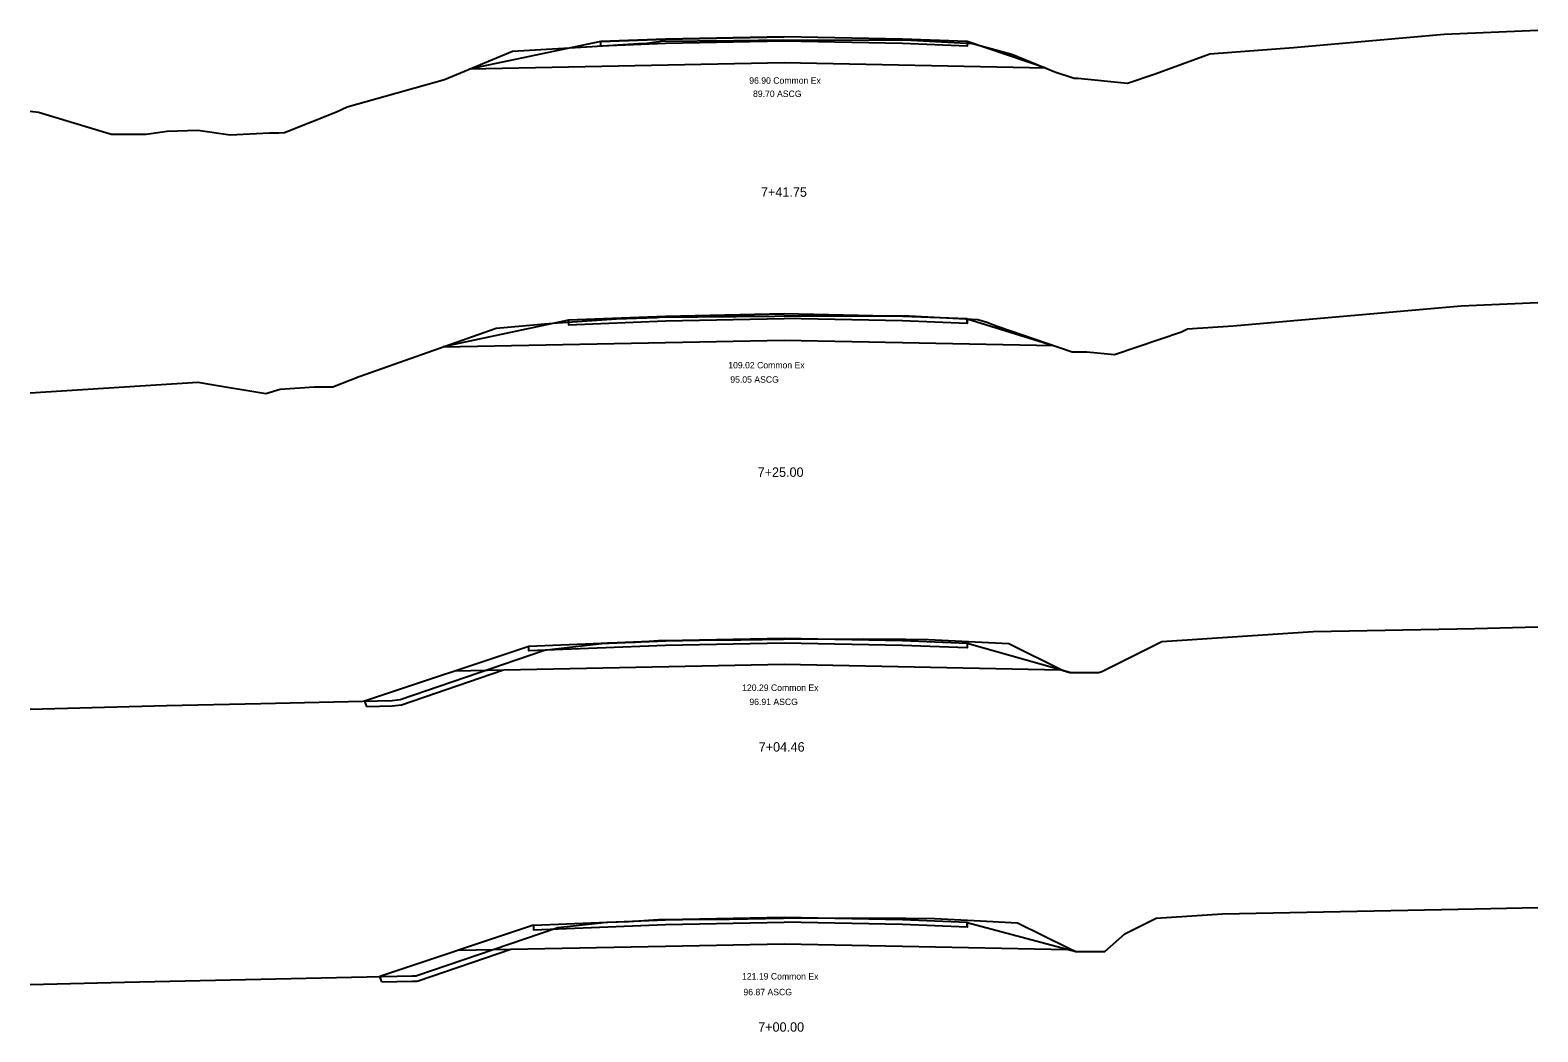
# Model space of a CAD drawing. Extents: x 2194004 to 2194525, y 863888 to 863998.
# Drawn here: x 2194385 to 2194525, y 863895.1 to 863988 of the extents above; entities that cross this region are included whole.
import ezdxf

# ---------------------------------------------------------------- set-up
doc = ezdxf.new("R2010")
doc.units = 0
for name, color, linetype in [('Approach', 7, 'Continuous'), ('H_V ANNOTATION', 7, 'Continuous'), ('S_Roadway_Centerline', 7, 'Continuous'), ('TEMPLATE', 7, 'Continuous')]:
    doc.layers.add(name, color=color, linetype=linetype)

msp = doc.modelspace()

# ---------------------------------------------------------------- linework, layer by layer
at = {"layer": 'S_Roadway_Centerline'}
for points in [[(2194384.99, 863980.53), (2194385.76, 863980.43), (2194392.02, 863978.54), (2194392.54, 863978.37), (2194395.76, 863978.39), (2194397.71, 863978.66), (2194400.57, 863978.76), (2194403.35, 863978.34), (2194403.57, 863978.33), (2194407.22, 863978.51), (2194408.07, 863978.51), (2194408.59, 863978.55), (2194413.42, 863980.46), (2194414.43, 863980.92), (2194423.45, 863983.47), (2194429.77, 863986.08), (2194437.17, 863986.52), (2194441.49, 863986.81), (2194442.24, 863986.84), (2194443.54, 863987.01), (2194450.34, 863987.07), (2194454.91, 863987.14), (2194459.64, 863987.12), (2194466.23, 863987.13), (2194468.49, 863987.01), (2194472.5, 863986.8), (2194476.14, 863985.8), (2194480.13, 863984.18), (2194481.92, 863983.57), (2194482.27, 863983.57), (2194486.89, 863983.12), (2194489.46, 863983.99), (2194494.52, 863985.83), (2194502.3, 863986.42), (2194516.28, 863987.66), (2194524.99, 863988.04)], [(2194384.99, 863954.36), (2194400.57, 863955.36), (2194401.83, 863955.13), (2194406.87, 863954.31), (2194408.21, 863954.7), (2194411.4, 863954.92), (2194413.08, 863954.93), (2194415.55, 863955.9), (2194428.25, 863960.36), (2194433.48, 863960.84), (2194439.44, 863961.24), (2194443.19, 863961.37), (2194443.42, 863961.4), (2194454.11, 863961.5), (2194454.96, 863961.51), (2194455.83, 863961.51), (2194466.22, 863961.53), (2194466.62, 863961.51), (2194472.97, 863961.18), (2194473.83, 863960.94), (2194474.78, 863960.56), (2194481.74, 863958.17), (2194483.1, 863958.17), (2194485.69, 863957.92), (2194491.9, 863960.03), (2194492.45, 863960.3), (2194496.68, 863960.58), (2194517.88, 863962.46), (2194524.99, 863962.76)], [(2194384.99, 863925.02), (2194397.64, 863925.35), (2194406.42, 863925.54), (2194418.59, 863925.82), (2194419.35, 863925.91), (2194432.66, 863930.45), (2194432.83, 863930.51), (2194432.96, 863930.52), (2194438.59, 863931.16), (2194441.16, 863931.24), (2194443.34, 863931.37), (2194450.98, 863931.44), (2194454.95, 863931.51), (2194462.37, 863931.53), (2194466.28, 863931.5), (2194468.39, 863931.48), (2194472.75, 863931.25), (2194475.86, 863931.1), (2194480.9, 863928.61), (2194481.52, 863928.4), (2194484.11, 863928.41), (2194484.22, 863928.4), (2194484.5, 863928.5), (2194490.06, 863931.29), (2194504.11, 863932.21), (2194519.14, 863932.5), (2194524.99, 863932.64)], [(2194384.99, 863899.44), (2194393.74, 863899.67), (2194420.46, 863900.26), (2194420.78, 863900.27), (2194420.83, 863900.27), (2194420.89, 863900.28), (2194420.89, 863900.28), (2194433.8, 863904.69), (2194434, 863904.73), (2194438.54, 863905.24), (2194440.57, 863905.31), (2194443.32, 863905.47), (2194449.92, 863905.53), (2194454.95, 863905.62), (2194461.36, 863905.63), (2194466.29, 863905.6), (2194468.97, 863905.57), (2194472.65, 863905.38), (2194476.66, 863905.18), (2194481.44, 863902.83), (2194482.09, 863902.5), (2194484.53, 863902.51), (2194484.77, 863902.5), (2194486.65, 863904.16), (2194489.54, 863905.62), (2194495.71, 863906.02), (2194519.17, 863906.47), (2194524.99, 863906.6)]]:
    msp.add_lwpolyline(points, dxfattribs=at)
at = {"layer": 'TEMPLATE'}
for p, q in [((2194437.99, 863986.97), (2194425.76, 863984.42)), ((2194437.99, 863986.97), (2194443.99, 863987.21)), ((2194443.99, 863987.21), (2194437.99, 863986.97)), ((2194437.99, 863986.97), (2194437.99, 863986.97)), ((2194443.99, 863987.21), (2194454.99, 863987.43)), ((2194454.99, 863987.43), (2194443.99, 863987.21)), ((2194454.99, 863987.01), (2194443.99, 863986.79)), ((2194465.99, 863987.21), (2194454.99, 863987.43)), ((2194465.99, 863986.79), (2194454.99, 863987.01)), ((2194471.99, 863986.97), (2194465.99, 863987.21)), ((2194479.29, 863984.52), (2194471.99, 863986.97)), ((2194454.99, 863985.01), (2194425.76, 863984.42)), ((2194479.29, 863984.52), (2194454.99, 863985.01)), ((2194434.97, 863961.11), (2194423.34, 863958.64)), ((2194443.99, 863961.47), (2194434.97, 863961.11)), ((2194443.99, 863961.47), (2194454.99, 863961.69)), ((2194454.99, 863961.69), (2194443.99, 863961.47)), ((2194443.99, 863961.05), (2194454.99, 863961.27)), ((2194465.99, 863961.47), (2194454.99, 863961.69)), ((2194465.99, 863961.05), (2194454.99, 863961.27)), ((2194471.99, 863961.23), (2194465.99, 863961.47)), ((2194471.99, 863961.23), (2194479.99, 863958.77)), ((2194431.28, 863930.84), (2194416.04, 863925.76)), ((2194443.99, 863931.35), (2194431.28, 863930.84)), ((2194437.99, 863931.11), (2194443.99, 863931.35)), ((2194437.99, 863931.11), (2194437.99, 863931.11)), ((2194443.99, 863931.35), (2194454.99, 863931.57)), ((2194454.99, 863931.57), (2194443.99, 863931.35)), ((2194454.99, 863931.15), (2194443.99, 863930.93)), ((2194465.99, 863931.35), (2194454.99, 863931.57)), ((2194465.99, 863930.93), (2194454.99, 863931.15)), ((2194471.99, 863931.11), (2194465.99, 863931.35)), ((2194481.52, 863928.4), (2194471.99, 863931.11)), ((2194454.99, 863929.15), (2194424.38, 863928.54)), ((2194480.7, 863928.63), (2194454.99, 863929.15)), ((2194416.04, 863925.76), (2194416.21, 863925.26)), ((2194443.99, 863905.44), (2194454.99, 863905.66)), ((2194454.99, 863905.66), (2194443.99, 863905.44)), ((2194443.99, 863905.02), (2194454.99, 863905.24)), ((2194465.99, 863905.44), (2194454.99, 863905.66)), ((2194465.99, 863905.02), (2194454.99, 863905.24)), ((2194471.99, 863905.2), (2194465.99, 863905.44)), ((2194471.99, 863905.2), (2194482.09, 863902.5)), ((2194431.73, 863904.95), (2194417.47, 863900.19))]:
    msp.add_line(p, q, dxfattribs=at)
for points in [[(2194443.99, 863986.79), (2194437.99, 863986.55), (2194437.99, 863986.97)], [(2194471.99, 863986.97), (2194471.99, 863986.55), (2194465.99, 863986.79)], [(2194434.97, 863961.11), (2194434.97, 863960.69), (2194443.99, 863961.05)], [(2194471.99, 863960.81), (2194471.99, 863961.23), (2194471.99, 863960.81), (2194465.99, 863961.05)], [(2194423.34, 863958.64), (2194443.99, 863959.05), (2194454.99, 863959.27), (2194465.99, 863959.05), (2194479.99, 863958.77)], [(2194443.99, 863930.93), (2194431.28, 863930.42), (2194431.28, 863930.84)], [(2194471.99, 863931.11), (2194471.99, 863930.69), (2194465.99, 863930.93)], [(2194416.21, 863925.26), (2194418.63, 863925.32), (2194419.46, 863925.42), (2194428.86, 863928.63)], [(2194431.73, 863904.95), (2194443.99, 863905.44)], [(2194431.73, 863904.95), (2194431.73, 863904.53), (2194443.99, 863905.02)], [(2194471.99, 863904.78), (2194471.99, 863905.2), (2194471.99, 863904.78), (2194465.99, 863905.02)], [(2194417.64, 863899.7), (2194420.47, 863899.76), (2194420.79, 863899.77), (2194420.89, 863899.77), (2194421.01, 863899.79), (2194421.03, 863899.8), (2194429.61, 863902.73)], [(2194424.8, 863902.64), (2194443.99, 863903.02), (2194454.99, 863903.24), (2194465.99, 863903.02), (2194481.3, 863902.71)], [(2194417.64, 863899.7), (2194417.47, 863900.19)]]:
    msp.add_lwpolyline(points, dxfattribs=at)

# ---------------------------------------------------------------- texts
at = {"layer": 'Approach'}
for s, p in [('96.90 Common Ex', (2194451.76, 863983.06)), ('89.70 ASCG', (2194452.11, 863981.83)), ('109.02 Common Ex', (2194449.81, 863956.64)), ('95.05 ASCG', (2194450, 863955.31)), ('120.29 Common Ex', (2194451.1, 863926.7)), ('96.91 ASCG', (2194451.77, 863925.39)), ('121.19 Common Ex', (2194451.09, 863899.91)), ('96.87 ASCG', (2194451.22, 863898.45))]:
    msp.add_text(s, height=0.6, dxfattribs=at).set_placement(p)
at = {"layer": 'H_V ANNOTATION'}
for s, p in [('7+41.75', (2194452.85, 863972.57)), ('7+25.00', (2194452.54, 863946.57)), ('7+04.46', (2194452.64, 863921.07)), ('7+00.00', (2194452.59, 863895.07))]:
    msp.add_text(s, height=0.875, dxfattribs=at).set_placement(p)
at = {"layer": 'TEMPLATE'}
for s, p in [('C', (2194454.91, 863987.14)), ('L', (2194454.91, 863987.13)), ('C', (2194454.95, 863931.51)), ('L', (2194454.95, 863931.5))]:
    msp.add_text(s, height=0.0146, dxfattribs=at).set_placement(p)

doc.saveas('drawing.dxf')
